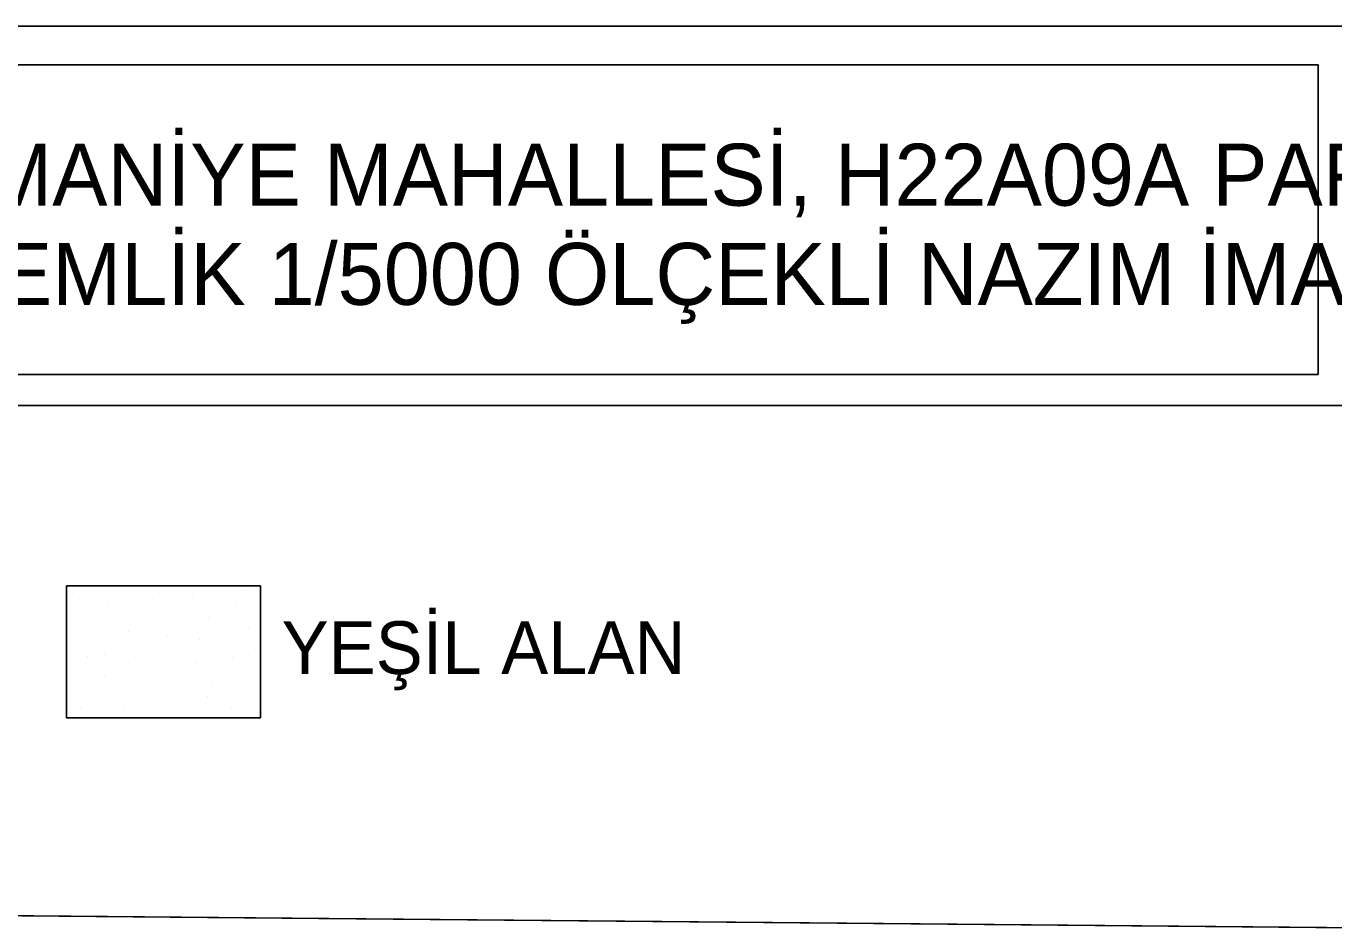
# Model space of a CAD drawing. Extents: x 427903 to 430077, y 4477233 to 4480385.
# Drawn here: x 428726 to 429260, y 4480020 to 4480385 of the extents above; entities that cross this region are included whole.
import ezdxf

# ---------------------------------------------------------------- set-up
doc = ezdxf.new("R2010")
doc.units = 0
for name, color, linetype in [('Default', 7, 'Continuous'), ('Level 53', 7, 'Continuous'), ('PL_AYA_ORMAN', 7, 'Continuous'), ('PL_AYA_PARK_DINLENME', 7, 'Continuous'), ('rezerv yapı alan', 7, 'Continuous'), ('SıNıR', 7, 'Continuous'), ('TR_PARKALANI', 7, 'Continuous')]:
    doc.layers.add(name, color=color, linetype=linetype)

# ---------------------------------------------------------------- blocks, each defined once
blk = doc.blocks.new('POINT_DISPLAY')
at = {"layer": 'Default'}
blk.add_line((0, 0), (0, 0), dxfattribs=at)

msp = doc.modelspace()

# ---------------------------------------------------------------- linework, layer by layer
at = {"layer": 'Level 53'}
for p, q in [((427919.44, 4480385.36), (429266.95, 4480385.36)), ((427932.36, 4480369.55), (429254.03, 4480369.55)), ((429254.03, 4480369.55), (429254.03, 4480243.03)), ((428290.69, 4480243.03), (429254.03, 4480243.03)), ((427919.44, 4480230.37), (429266.95, 4480230.37))]:
    msp.add_line(p, q, dxfattribs=at)
msp.add_lwpolyline([(428742.71, 4480102.72), (428821.95, 4480102.72), (428821.95, 4480156.6), (428742.71, 4480156.6), (428742.71, 4480102.72)], dxfattribs=at)
at = {"layer": 'PL_AYA_ORMAN'}
msp.add_lwpolyline([(429043.16, 4480018.9), (427934.93, 4480028.9)], dxfattribs=at)
at = {"layer": 'PL_AYA_PARK_DINLENME'}
msp.add_lwpolyline([(428742.71, 4480156.6), (428742.71, 4480102.72), (428821.95, 4480102.72), (428821.95, 4480156.6), (428742.71, 4480156.6)], dxfattribs=at)
at = {"layer": 'rezerv yapı alan'}
msp.add_lwpolyline([(430040.04, 4478910.67), (430050.52, 4480009.82), (427929.02, 4480028.95), (427921.98, 4479290.57)], dxfattribs=at)
at = {"layer": 'SıNıR'}
msp.add_line((427929.02, 4480028.95), (430050.52, 4480009.82), dxfattribs=at)

# ---------------------------------------------------------------- block references
at = {"layer": 'TR_PARKALANI', "xscale": 0.1, "yscale": 0.10000000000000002}
for p in [(428815.97, 4480154.92), (428815.97, 4480154.92), (428747.74, 4480151.17), (428747.74, 4480151.17), (428773.36, 4480152.92), (428773.36, 4480152.92), (428780.46, 4480153.76), (428780.46, 4480153.76), (428794.32, 4480152.04), (428794.32, 4480152.04), (428811.9, 4480149.98), (428811.9, 4480149.98), (428759.68, 4480148.84), (428759.68, 4480148.84), (428755.31, 4480139.82), (428755.31, 4480139.82), (428775.22, 4480138.91), (428775.22, 4480138.91), (428782.96, 4480142.73), (428782.96, 4480142.73), (428790.07, 4480143.57), (428790.07, 4480143.57), (428800.84, 4480143.57), (428800.84, 4480143.57), (428809.75, 4480138.65), (428809.75, 4480138.65), (428816.85, 4480139.5), (428816.85, 4480139.5), (428768.12, 4480138.07), (428768.12, 4480138.07), (428783.95, 4480136.29), (428783.95, 4480136.29), (428796.94, 4480134.87), (428796.94, 4480134.87), (428758.34, 4480128.43), (428758.34, 4480128.43), (428780.17, 4480129.31), (428780.17, 4480129.31), (428817.43, 4480128.14), (428817.43, 4480128.14), (428751.24, 4480127.59), (428751.24, 4480127.59), (428770.56, 4480127.56), (428770.56, 4480127.56), (428788.5, 4480124.1), (428788.5, 4480124.1), (428795.6, 4480124.94), (428795.6, 4480124.94), (428810.33, 4480127.3), (428810.33, 4480127.3), (428758.34, 4480119.7), (428758.34, 4480119.7), (428769.98, 4480119.7), (428769.98, 4480119.7), (428802.29, 4480117.37), (428802.29, 4480117.37), (428817.72, 4480118.25), (428817.72, 4480118.25), (428780.46, 4480114.17), (428780.46, 4480114.17), (428755.6, 4480109.54), (428755.6, 4480109.54), (428785.29, 4480108.09), (428785.29, 4480108.09), (428800.43, 4480111.29), (428800.43, 4480111.29), (428748.33, 4480106.34), (428748.33, 4480106.34), (428766.37, 4480106.34), (428766.37, 4480106.34), (428810.04, 4480106.34), (428810.04, 4480106.34)]:
    msp.add_blockref('POINT_DISPLAY', p, dxfattribs=at)

# ---------------------------------------------------------------- texts
at = {"layer": 'Level 53'}
for s, height, p in [('GEMLİK BELEDİYESİ OSMANİYE MAHALLESİ, H22A09A PAFTA, 1064/1 VE 1076/5 ', 25.3046, (428315.64, 4480311.99)), ('ADA/PARSELLERE AİT GEMLİK 1/5000 ÖLÇEKLİ NAZIM İMAR PLANI DEĞİŞİKLİĞİ', 25.3046, (428315.64, 4480271.46)), ('YEŞİL ALAN', 21.553, (428830.57, 4480120.58))]:
    msp.add_text(s, height=height, rotation=360, dxfattribs=at).set_placement(p)

doc.saveas('drawing.dxf')
